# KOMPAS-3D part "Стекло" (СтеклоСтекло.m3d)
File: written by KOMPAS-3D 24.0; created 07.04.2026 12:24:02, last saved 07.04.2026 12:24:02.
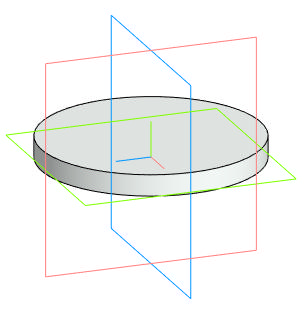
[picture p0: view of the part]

Document properties: Автор: Main; Полное имя файла: D:\DN.ru Аутсерс\Стекло смотровое DN.ru\Исходники\Стекло смотровое DN.ru SG2-34G-F тип В ГОСТ 21836-2021 Ду15 Ру40, углеродистая сталь, фланцевое\СтеклоСтекло.m3d

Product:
- Body: Твердое тело1  | qty 1
- Part/product: Стекло

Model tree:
1. Твердое тело1  (labels: Твердое тело1)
